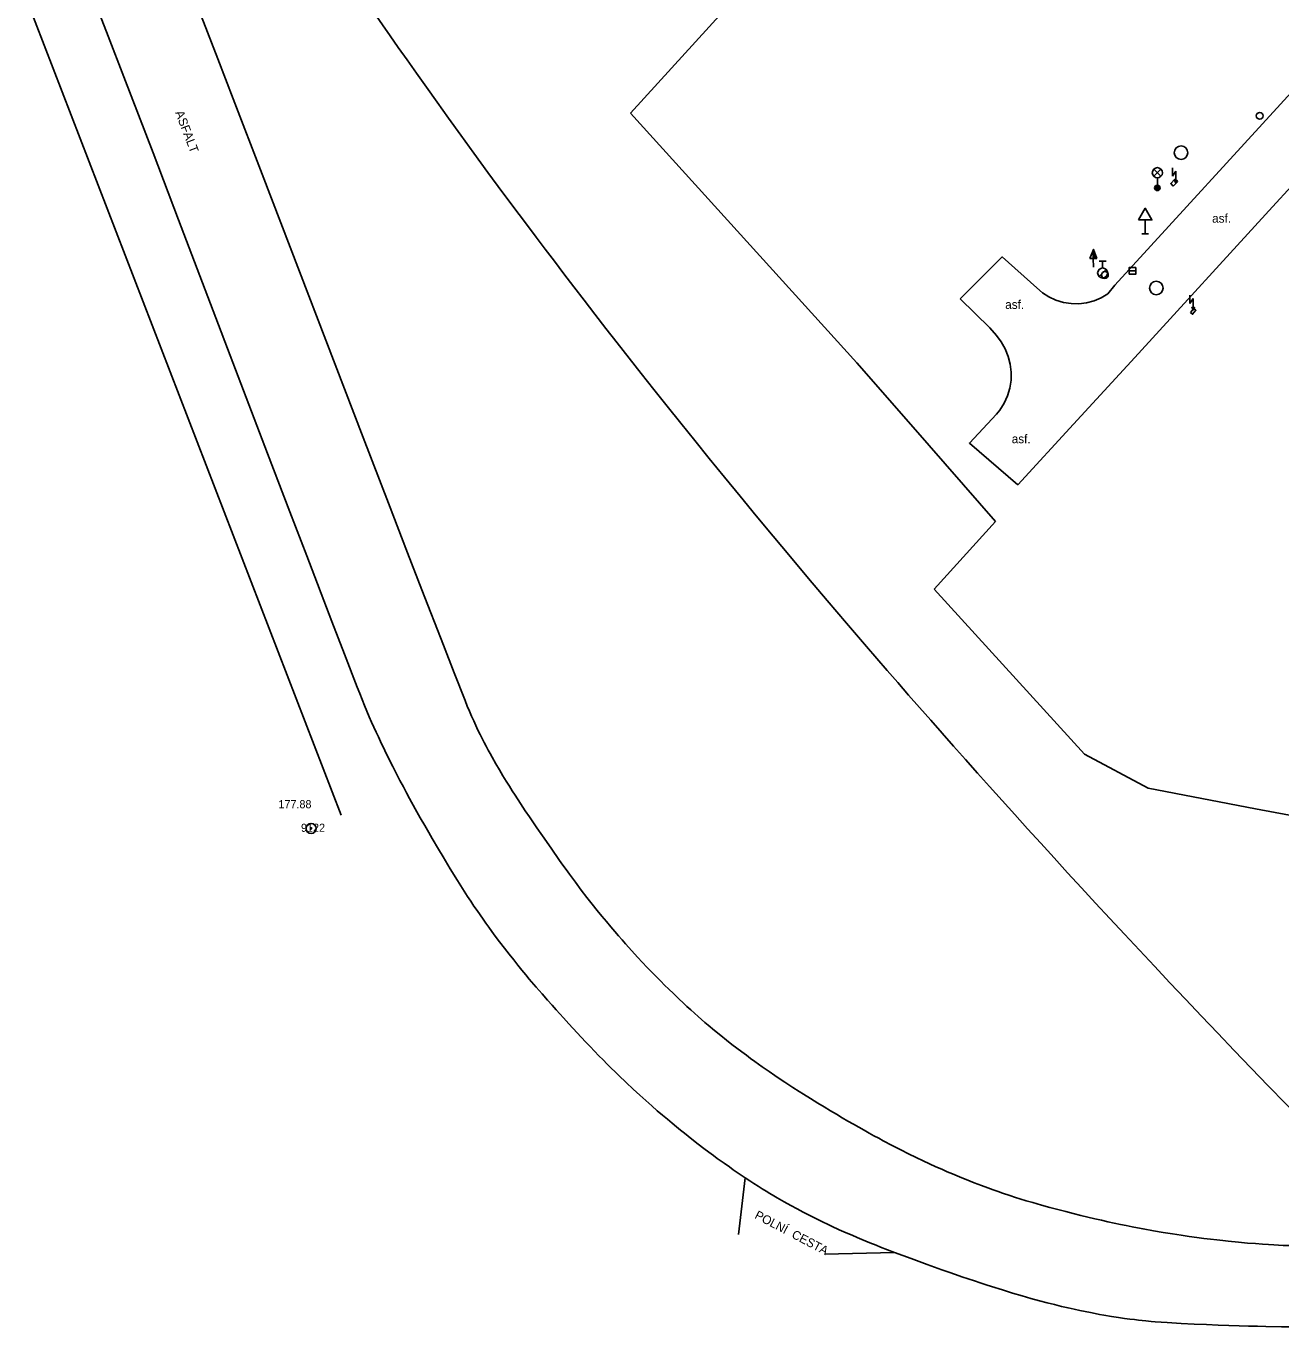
# Model space of a CAD drawing. Extents: x -540235 to -537963, y -1184915 to -1183660.
# Drawn here: x -538404.9 to -538311.8, y -1183916.4 to -1183819.9 of the extents above; entities that cross this region are included whole.
import ezdxf

# ---------------------------------------------------------------- set-up
doc = ezdxf.new("R2010")
doc.units = 0
for name, color, linetype in [('Vrstva 10', 7, 'Continuous'), ('Vrstva 11', 7, 'Continuous'), ('Vrstva 13', 7, 'Continuous'), ('Vrstva 21', 7, 'Continuous'), ('Vrstva 22', 7, 'Continuous'), ('Vrstva 23', 7, 'Continuous'), ('Vrstva 24', 7, 'Continuous'), ('Vrstva 27', 7, 'Continuous'), ('Vrstva 28', 7, 'Continuous'), ('Vrstva 33', 7, 'Continuous'), ('Vrstva 34', 7, 'Continuous'), ('Vrstva 40', 7, 'Continuous'), ('Vrstva 7', 7, 'Continuous'), ('Vrstva 8', 7, 'Continuous')]:
    doc.layers.add(name, color=color, linetype=linetype)

msp = doc.modelspace()

# ---------------------------------------------------------------- linework, layer by layer
at = {"layer": 'Vrstva 10'}
for p, q in [((-538391.89, -1183819.108), (-538390.663, -1183822.28)), ((-538398.784, -1183820.596), (-538397.625, -1183823.613)), ((-538390.663, -1183822.28), (-538389.515, -1183825.255)), ((-538397.625, -1183823.613), (-538395.458, -1183829.272)), ((-538310.506, -1183824.18), (-538324.131, -1183839.082)), ((-538389.515, -1183825.255), (-538387.369, -1183830.836)), ((-538312.432, -1183833.267), (-538306.639, -1183826.91)), ((-538395.458, -1183829.272), (-538393.567, -1183834.225)), ((-538387.369, -1183830.836), (-538379.877, -1183850.377)), ((-538322.644, -1183844.434), (-538312.432, -1183833.267)), ((-538393.567, -1183834.225), (-538386.961, -1183851.567)), ((-538324.131, -1183839.082), (-538324.645, -1183839.719)), ((-538327.187, -1183849.377), (-538322.644, -1183844.434)), ((-538331.317, -1183853.88), (-538327.187, -1183849.377)), ((-538379.877, -1183850.377), (-538377.999, -1183855.261)), ((-538384.065, -1183859.153), (-538382.196, -1183864.028)), ((-538361.189, -1183897.438), (-538360.91, -1183897.709)), ((-538347.554, -1183898.885), (-538347.211, -1183899.103)), ((-538338.875, -1183903.783), (-538338.355, -1183904.032)), ((-538329.58, -1183907.323), (-538328.96, -1183907.495)), ((-538335.952, -1183912.47), (-538335.469, -1183912.637)), ((-538325.946, -1183915.301), (-538325.594, -1183915.368))]:
    msp.add_line(p, q, dxfattribs=at)
for points in [[(-538401.35, -1183813.95), (-538400.024, -1183817.38), (-538398.784, -1183820.596)], [(-538329.929, -1183839.271), (-538332.479, -1183836.985), (-538335.597, -1183840.099)], [(-538324.645, -1183839.719), (-538325.14, -1183840.014), (-538325.671, -1183840.238), (-538326.228, -1183840.386), (-538326.8, -1183840.456), (-538327.376, -1183840.446), (-538327.946, -1183840.357), (-538328.497, -1183840.189), (-538329.02, -1183839.947), (-538329.505, -1183839.635), (-538329.929, -1183839.271)], [(-538335.597, -1183840.099), (-538333.396, -1183842.244), (-538332.912, -1183842.809)], [(-538332.912, -1183842.809), (-538332.551, -1183843.284), (-538332.257, -1183843.803), (-538332.034, -1183844.357), (-538331.888, -1183844.936), (-538331.82, -1183845.528), (-538331.832, -1183846.125), (-538331.924, -1183846.715), (-538332.093, -1183847.287), (-538332.338, -1183847.831), (-538332.653, -1183848.338), (-538332.907, -1183848.659)], [(-538332.907, -1183848.659), (-538334.919, -1183850.797), (-538331.317, -1183853.88)], [(-538386.961, -1183851.567), (-538385.307, -1183855.903), (-538384.065, -1183859.153)], [(-538377.999, -1183855.261), (-538376.586, -1183858.923), (-538375.524, -1183861.668)], [(-538375.524, -1183861.668), (-538373.926, -1183865.785), (-538373.124, -1183867.843), (-538372.32, -1183869.9), (-538372.16, -1183870.299), (-538372, -1183870.684)], [(-538382.196, -1183864.028), (-538381.259, -1183866.464), (-538380.32, -1183868.9), (-538380.136, -1183869.37), (-538379.954, -1183869.824), (-538379.774, -1183870.261), (-538379.597, -1183870.684), (-538379.422, -1183871.091), (-538379.249, -1183871.485), (-538379.08, -1183871.865), (-538378.913, -1183872.233), (-538378.75, -1183872.587), (-538378.59, -1183872.93)], [(-538372, -1183870.684), (-538371.84, -1183871.053), (-538371.68, -1183871.409), (-538371.522, -1183871.752), (-538371.365, -1183872.082), (-538371.209, -1183872.401), (-538371.055, -1183872.707), (-538370.903, -1183873.003), (-538370.753, -1183873.288), (-538370.606, -1183873.564), (-538370.461, -1183873.829), (-538370.319, -1183874.086), (-538370.039, -1183874.58)], [(-538378.59, -1183872.93), (-538378.274, -1183873.592), (-538377.971, -1183874.209), (-538377.683, -1183874.786), (-538377.407, -1183875.324), (-538377.146, -1183875.828), (-538376.897, -1183876.298), (-538376.662, -1183876.738), (-538376.439, -1183877.149), (-538376.015, -1183877.918), (-538375.638, -1183878.589), (-538375.304, -1183879.174), (-538375.009, -1183879.685), (-538374.749, -1183880.131), (-538374.289, -1183880.911), (-538373.941, -1183881.494)], [(-538370.039, -1183874.58), (-538369.77, -1183875.041), (-538369.514, -1183875.47), (-538369.269, -1183875.871), (-538369.037, -1183876.245), (-538368.816, -1183876.595), (-538368.607, -1183876.921), (-538368.21, -1183877.531)], [(-538368.21, -1183877.531), (-538367.858, -1183878.063), (-538367.546, -1183878.526), (-538366.995, -1183879.335), (-538366.576, -1183879.94), (-538365.945, -1183880.845), (-538365.31, -1183881.75), (-538365.063, -1183882.1), (-538364.821, -1183882.438), (-538364.586, -1183882.763), (-538364.357, -1183883.076), (-538364.134, -1183883.377), (-538363.698, -1183883.957), (-538363.284, -1183884.495), (-538362.892, -1183884.995), (-538362.521, -1183885.46)], [(-538373.941, -1183881.494), (-538373.413, -1183882.368), (-538372.88, -1183883.24), (-538372.626, -1183883.65), (-538372.376, -1183884.043), (-538372.132, -1183884.422), (-538371.893, -1183884.786), (-538371.658, -1183885.137), (-538371.429, -1183885.474), (-538371.205, -1183885.799), (-538370.986, -1183886.112), (-538370.772, -1183886.414), (-538370.563, -1183886.705), (-538370.153, -1183887.265), (-538369.764, -1183887.785), (-538369.394, -1183888.268), (-538369.044, -1183888.719), (-538368.712, -1183889.138), (-538368.398, -1183889.529)], [(-538362.521, -1183885.46), (-538362.169, -1183885.892), (-538361.836, -1183886.295), (-538361.522, -1183886.669), (-538361.225, -1183887.019), (-538360.944, -1183887.344), (-538360.678, -1183887.648), (-538360.428, -1183887.931), (-538359.953, -1183888.459), (-538359.533, -1183888.918), (-538359.161, -1183889.316), (-538358.833, -1183889.662), (-538358.543, -1183889.964), (-538358.288, -1183890.227), (-538357.837, -1183890.685), (-538357.495, -1183891.026), (-538357.236, -1183891.281), (-538356.845, -1183891.661), (-538356.45, -1183892.04), (-538356.153, -1183892.32), (-538355.865, -1183892.587)], [(-538368.398, -1183889.529), (-538368.101, -1183889.894), (-538367.82, -1183890.234)], [(-538367.82, -1183890.234), (-538367.555, -1183890.552), (-538367.053, -1183891.145), (-538366.609, -1183891.661), (-538366.217, -1183892.11), (-538365.871, -1183892.501), (-538365.566, -1183892.842), (-538365.027, -1183893.438), (-538364.62, -1183893.882), (-538364.003, -1183894.547), (-538363.38, -1183895.21), (-538363.04, -1183895.567), (-538362.71, -1183895.91), (-538362.388, -1183896.24), (-538362.076, -1183896.557), (-538361.772, -1183896.862), (-538361.477, -1183897.155), (-538361.189, -1183897.438)], [(-538355.865, -1183892.587), (-538355.584, -1183892.844), (-538355.31, -1183893.09)], [(-538355.31, -1183893.09), (-538355.044, -1183893.325), (-538354.785, -1183893.551), (-538354.533, -1183893.769), (-538354.289, -1183893.977), (-538353.811, -1183894.376), (-538353.36, -1183894.744), (-538352.934, -1183895.084), (-538352.533, -1183895.398), (-538352.153, -1183895.69), (-538351.796, -1183895.96), (-538351.459, -1183896.211), (-538351.141, -1183896.445), (-538350.842, -1183896.661), (-538350.276, -1183897.064), (-538349.777, -1183897.411), (-538349.338, -1183897.712), (-538348.95, -1183897.973), (-538348.609, -1183898.199), (-538348.008, -1183898.593), (-538347.554, -1183898.885)], [(-538360.91, -1183897.709), (-538360.366, -1183898.23), (-538359.851, -1183898.713), (-538359.366, -1183899.16), (-538358.907, -1183899.575), (-538358.474, -1183899.96), (-538358.065, -1183900.318), (-538357.679, -1183900.65), (-538357.315, -1183900.958), (-538356.971, -1183901.246), (-538356.648, -1183901.513), (-538356.342, -1183901.762), (-538356.055, -1183901.993), (-538355.511, -1183902.424), (-538355.031, -1183902.797), (-538354.607, -1183903.12), (-538354.234, -1183903.4), (-538353.904, -1183903.643), (-538353.615, -1183903.855)], [(-538347.211, -1183899.103), (-538346.692, -1183899.427), (-538346.17, -1183899.75), (-538345.692, -1183900.041), (-538345.229, -1183900.32), (-538344.781, -1183900.588), (-538344.345, -1183900.845), (-538343.923, -1183901.091), (-538343.514, -1183901.326), (-538343.117, -1183901.552), (-538342.732, -1183901.769), (-538342.358, -1183901.976), (-538341.996, -1183902.175), (-538341.644, -1183902.366), (-538341.303, -1183902.549), (-538340.64, -1183902.898), (-538340.015, -1183903.218), (-538339.428, -1183903.513), (-538338.875, -1183903.783)], [(-538353.615, -1183903.855), (-538353.104, -1183904.222), (-538352.717, -1183904.495), (-538352.426, -1183904.698), (-538351.985, -1183905), (-538351.54, -1183905.3), (-538351.212, -1183905.517), (-538350.893, -1183905.725), (-538350.583, -1183905.922), (-538350.282, -1183906.111), (-538349.99, -1183906.291), (-538349.706, -1183906.463), (-538349.431, -1183906.627), (-538349.163, -1183906.785), (-538348.643, -1183907.084), (-538348.153, -1183907.357), (-538347.691, -1183907.608), (-538347.257, -1183907.838), (-538346.847, -1183908.05), (-538346.462, -1183908.246), (-538346.1, -1183908.426), (-538345.758, -1183908.592), (-538345.437, -1183908.745), (-538345.135, -1183908.887)], [(-538338.355, -1183904.032), (-538337.865, -1183904.261), (-538337.404, -1183904.472), (-538336.97, -1183904.666), (-538336.562, -1183904.845), (-538336.178, -1183905.01), (-538335.816, -1183905.162), (-538335.477, -1183905.303), (-538335.157, -1183905.433), (-538334.554, -1183905.671), (-538334.024, -1183905.874), (-538333.558, -1183906.047), (-538333.148, -1183906.195), (-538332.787, -1183906.322), (-538332.471, -1183906.431), (-538331.914, -1183906.617), (-538331.494, -1183906.753), (-538331.177, -1183906.853), (-538330.7, -1183906.998), (-538330.22, -1183907.14), (-538329.58, -1183907.323)], [(-538328.96, -1183907.495), (-538328.358, -1183907.657), (-538327.776, -1183907.81)], [(-538327.776, -1183907.81), (-538327.211, -1183907.955), (-538326.664, -1183908.091), (-538326.134, -1183908.219), (-538325.62, -1183908.34), (-538325.123, -1183908.453), (-538324.64, -1183908.561), (-538324.173, -1183908.662), (-538323.719, -1183908.757), (-538323.28, -1183908.847), (-538322.855, -1183908.932), (-538322.442, -1183909.012), (-538322.043, -1183909.087), (-538321.268, -1183909.227), (-538320.541, -1183909.352), (-538319.86, -1183909.462), (-538319.22, -1183909.56), (-538318.62, -1183909.647), (-538318.057, -1183909.725)], [(-538345.135, -1183908.887), (-538344.566, -1183909.149), (-538344.065, -1183909.373), (-538343.624, -1183909.566), (-538343.237, -1183909.732), (-538342.896, -1183909.875), (-538342.296, -1183910.121), (-538341.844, -1183910.302), (-538341.503, -1183910.436), (-538340.988, -1183910.635), (-538340.47, -1183910.83), (-538339.225, -1183911.292), (-538338.057, -1183911.72), (-538336.963, -1183912.114), (-538336.449, -1183912.296), (-538335.952, -1183912.47)], [(-538318.057, -1183909.725), (-538317.529, -1183909.794), (-538317.034, -1183909.855), (-538316.569, -1183909.909), (-538316.134, -1183909.958), (-538315.725, -1183910.001), (-538314.958, -1183910.076), (-538314.287, -1183910.135), (-538313.699, -1183910.182), (-538313.184, -1183910.219), (-538312.733, -1183910.249), (-538312.339, -1183910.273), (-538311.647, -1183910.309), (-538311.129, -1183910.332), (-538310.739, -1183910.347), (-538310.155, -1183910.366), (-538309.57, -1183910.38)], [(-538335.469, -1183912.637), (-538335.002, -1183912.797), (-538334.549, -1183912.95), (-538334.11, -1183913.096), (-538333.684, -1183913.236), (-538333.272, -1183913.369), (-538332.471, -1183913.621), (-538331.72, -1183913.85), (-538331.015, -1183914.058), (-538330.352, -1183914.246), (-538329.731, -1183914.416), (-538329.147, -1183914.57), (-538328.599, -1183914.709), (-538328.084, -1183914.835), (-538327.601, -1183914.948), (-538327.147, -1183915.05), (-538326.721, -1183915.143), (-538326.321, -1183915.226), (-538325.946, -1183915.301)], [(-538325.594, -1183915.368), (-538325.263, -1183915.43), (-538324.953, -1183915.485), (-538324.37, -1183915.583), (-538323.858, -1183915.662), (-538323.41, -1183915.726), (-538323.018, -1183915.779), (-538322.673, -1183915.822), (-538322.372, -1183915.857), (-538321.843, -1183915.914), (-538321.446, -1183915.951), (-538321.148, -1183915.977), (-538320.699, -1183916.011), (-538320.25, -1183916.04), (-538319.213, -1183916.098), (-538318.241, -1183916.147), (-538317.33, -1183916.189), (-538316.475, -1183916.224), (-538315.674, -1183916.253)], [(-538315.674, -1183916.253), (-538314.923, -1183916.278), (-538314.219, -1183916.298), (-538313.559, -1183916.314), (-538312.941, -1183916.328), (-538311.78, -1183916.347), (-538310.765, -1183916.359), (-538309.877, -1183916.364), (-538309.1, -1183916.365), (-538308.419, -1183916.363), (-538307.229, -1183916.354), (-538306.337, -1183916.342)]]:
    msp.add_lwpolyline(points, dxfattribs=at)
at = {"layer": 'Vrstva 11'}
for p, q in [((-538351.54, -1183905.3), (-538352.03, -1183909.5)), ((-538345.67, -1183910.97), (-538340.47, -1183910.83))]:
    msp.add_line(p, q, dxfattribs=at)
at = {"layer": 'Vrstva 13'}
for p, q in [((-538369.508, -1183832.222), (-538370.626, -1183830.707)), ((-538363.486, -1183840.201), (-538364.249, -1183839.208)), ((-538356.33, -1183849.309), (-538357.338, -1183848.049)), ((-538349.479, -1183857.694), (-538350.724, -1183856.192)), ((-538342.543, -1183865.889), (-538344.031, -1183864.154)), ((-538336.085, -1183873.284), (-538336.944, -1183872.313)), ((-538328.639, -1183881.564), (-538329.629, -1183880.477)), ((-538321.191, -1183889.609), (-538322.313, -1183888.411))]:
    msp.add_line(p, q, dxfattribs=at)
for points in [[(-538377.271, -1183821.446), (-538377.875, -1183820.581), (-538378.441, -1183819.769), (-538379.496, -1183818.243), (-538380.415, -1183816.904), (-538381.216, -1183815.729), (-538381.914, -1183814.699), (-538382.523, -1183813.796)], [(-538375.932, -1183823.347), (-538376.624, -1183822.367), (-538377.271, -1183821.446)], [(-538370.626, -1183830.707), (-538371.668, -1183829.282), (-538372.642, -1183827.943), (-538373.55, -1183826.685), (-538374.399, -1183825.502), (-538375.192, -1183824.391), (-538375.932, -1183823.347)], [(-538364.249, -1183839.208), (-538364.986, -1183838.243), (-538365.697, -1183837.308), (-538366.385, -1183836.399), (-538367.049, -1183835.518), (-538367.691, -1183834.663), (-538368.311, -1183833.833), (-538369.508, -1183832.222)], [(-538357.338, -1183848.049), (-538358.311, -1183846.826), (-538359.25, -1183845.638), (-538360.158, -1183844.485), (-538361.034, -1183843.366), (-538361.88, -1183842.28), (-538362.697, -1183841.225), (-538363.486, -1183840.201)], [(-538350.724, -1183856.192), (-538351.926, -1183854.734), (-538353.086, -1183853.317), (-538354.206, -1183851.942), (-538355.287, -1183850.606), (-538356.33, -1183849.309)], [(-538344.031, -1183864.154), (-538345.466, -1183862.468), (-538346.852, -1183860.83), (-538348.189, -1183859.239), (-538349.479, -1183857.694)], [(-538336.944, -1183872.313), (-538337.787, -1183871.356), (-538338.615, -1183870.412), (-538339.429, -1183869.482), (-538340.228, -1183868.564), (-538341.014, -1183867.66), (-538341.785, -1183866.768), (-538342.543, -1183865.889)], [(-538329.629, -1183880.477), (-538330.601, -1183879.406), (-538331.556, -1183878.349), (-538332.495, -1183877.308), (-538333.416, -1183876.28), (-538334.322, -1183875.268), (-538335.211, -1183874.269), (-538336.085, -1183873.284)], [(-538322.313, -1183888.411), (-538323.415, -1183887.23), (-538324.497, -1183886.065), (-538325.56, -1183884.916), (-538326.605, -1183883.783), (-538327.631, -1183882.666), (-538328.639, -1183881.564)], [(-538315.271, -1183895.856), (-538316.498, -1183894.571), (-538317.703, -1183893.305), (-538318.886, -1183892.056), (-538320.049, -1183890.824), (-538321.191, -1183889.609)], [(-538308.8, -1183902.55), (-538310.141, -1183901.174), (-538311.458, -1183899.817), (-538312.752, -1183898.478), (-538314.023, -1183897.158), (-538315.271, -1183895.856)]]:
    msp.add_lwpolyline(points, dxfattribs=at)
at = {"layer": 'Vrstva 21'}
for radius in [0.375, 0.05]:
    msp.add_circle((-538383.74, -1183879.38), radius, dxfattribs=at)
at = {"layer": 'Vrstva 24'}
for p, q in [((-538319.86, -1183830.372), (-538319.86, -1183830.998)), ((-538319.86, -1183830.998), (-538319.61, -1183830.623)), ((-538319.72, -1183831.253), (-538319.61, -1183831.498)), ((-538319.61, -1183830.623), (-538319.61, -1183831.498)), ((-538319.61, -1183831.498), (-538319.5, -1183831.253)), ((-538318.572, -1183839.809), (-538318.572, -1183840.435)), ((-538318.572, -1183840.435), (-538318.322, -1183840.06)), ((-538318.432, -1183840.69), (-538318.322, -1183840.935)), ((-538318.322, -1183840.06), (-538318.322, -1183840.935)), ((-538318.322, -1183840.935), (-538318.212, -1183840.69))]:
    msp.add_line(p, q, dxfattribs=at)
for points in [[(-538319.8, -1183831.73), (-538319.991, -1183831.545), (-538319.671, -1183831.215), (-538319.48, -1183831.4), (-538319.8, -1183831.73)], [(-538318.52, -1183841.11), (-538318.363, -1183841.236), (-538318.123, -1183840.936), (-538318.28, -1183840.81), (-538318.52, -1183841.11)]]:
    msp.add_lwpolyline(points, dxfattribs=at)
at = {"layer": 'Vrstva 27'}
msp.add_line((-538323.078, -1183838.019), (-538322.578, -1183838.019), dxfattribs=at)
msp.add_lwpolyline([(-538323.078, -1183838.269), (-538322.578, -1183838.269), (-538322.578, -1183837.769), (-538323.078, -1183837.769)], close=True, dxfattribs=at)
for centre in [(-538319.221, -1183829.249), (-538321.06, -1183839.288)]:
    msp.add_circle(centre, 0.5, dxfattribs=at)
at = {"layer": 'Vrstva 28'}
for p, q in [((-538325.977, -1183837.099), (-538325.726, -1183836.425)), ((-538325.727, -1183837.099), (-538325.977, -1183837.099)), ((-538325.726, -1183837.751), (-538325.727, -1183837.1)), ((-538325.293, -1183838.446), (-538324.763, -1183837.916)), ((-538325.285, -1183837.299), (-538324.785, -1183837.299)), ((-538325.035, -1183837.799), (-538325.035, -1183837.299))]:
    msp.add_line(p, q, dxfattribs=at)
for points in [[(-538325.476, -1183837.1), (-538325.727, -1183837.1), (-538325.726, -1183836.425), (-538325.476, -1183837.1)], [(-538325.533, -1183837.06), (-538325.687, -1183837.06), (-538325.686, -1183836.647)], [(-538325.591, -1183837.02), (-538325.647, -1183837.02), (-538325.647, -1183836.87)]]:
    msp.add_lwpolyline(points, close=True, dxfattribs=at)
for centre, radius in [((-538313.389, -1183826.513), 0.25), ((-538325.035, -1183838.174), 0.375), ((-538324.869, -1183838.323), 0.25)]:
    msp.add_circle(centre, radius, dxfattribs=at)
at = {"layer": 'Vrstva 33'}
for p, q in [((-538321.244, -1183830.999), (-538320.714, -1183830.469)), ((-538321.244, -1183830.469), (-538320.714, -1183830.999)), ((-538320.979, -1183831.109), (-538320.979, -1183831.859))]:
    msp.add_line(p, q, dxfattribs=at)
for centre, radius in [((-538320.979, -1183830.734), 0.375), ((-538320.979, -1183831.859), 0.2), ((-538320.979, -1183831.859), 0.1445), ((-538320.979, -1183831.859), 0.0876)]:
    msp.add_circle(centre, radius, dxfattribs=at)
at = {"layer": 'Vrstva 34'}
for p, q in [((-538321.876, -1183834.239), (-538321.876, -1183835.257)), ((-538322.126, -1183835.257), (-538321.626, -1183835.257))]:
    msp.add_line(p, q, dxfattribs=at)
msp.add_lwpolyline([(-538322.376, -1183834.239), (-538321.376, -1183834.239), (-538321.876, -1183833.373)], close=True, dxfattribs=at)
at = {"layer": 'Vrstva 7'}
for p, q in [((-538360.04, -1183826.31), (-538322.96, -1183785.49)), ((-538404.88, -1183817.79), (-538381.5, -1183878.39)), ((-538343.27, -1183844.85), (-538360.04, -1183826.31)), ((-538332.98, -1183856.61), (-538339.1, -1183849.6)), ((-538337.52, -1183861.64), (-538332.98, -1183856.61)), ((-538326.39, -1183873.88), (-538337.52, -1183861.64)), ((-538321.65, -1183876.4), (-538326.39, -1183873.88)), ((-538311.19, -1183878.4), (-538313.7, -1183877.93))]:
    msp.add_line(p, q, dxfattribs=at)
at = {"layer": 'Vrstva 8'}
for p, q in [((-538339.1, -1183849.6), (-538343.27, -1183844.85)), ((-538313.7, -1183877.93), (-538321.65, -1183876.4))]:
    msp.add_line(p, q, dxfattribs=at)

# ---------------------------------------------------------------- texts
at = {"layer": 'Vrstva 22'}
msp.add_text('177.88', height=0.6, dxfattribs=at).set_placement((-538386.165, -1183877.88))
at = {"layer": 'Vrstva 23'}
msp.add_text('9122', height=0.6, dxfattribs=at).set_placement((-538384.49, -1183879.63))
at = {"layer": 'Vrstva 40'}
for s, height, rotation, p in [('ASFALT', 0.65, 290.931367, (-538393.833, -1183826.267)), ('POLNÍ  CESTA', 0.649998, 332.317386, (-538350.898, -1183908.271))]:
    msp.add_text(s, height=height, rotation=rotation, dxfattribs=at).set_placement(p)
for p in [(-538316.916, -1183834.441), (-538332.259, -1183840.837), (-538331.777, -1183850.804)]:
    msp.add_text('asf.', height=0.65, dxfattribs=at).set_placement(p)

doc.saveas('drawing.dxf')
